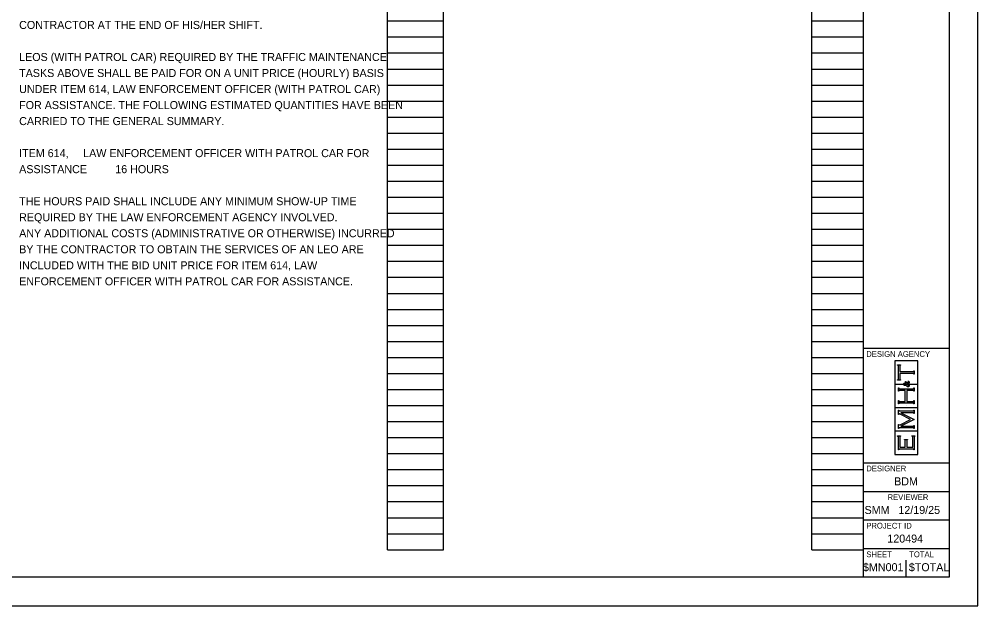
# Model space of a CAD drawing. Extents: x 0 to 34, y 0 to 22.
# Drawn here: x 17.24 to 34, y 0 to 10.25 of the extents above; entities that cross this region are included whole.
import ezdxf

# ---------------------------------------------------------------- set-up
doc = ezdxf.new("R2010")
doc.units = 0
for name, color, linetype in [('SH_Border', 7, 'Continuous'), ('SH_Cut_Line', 7, 'Continuous'), ('SH_Data', 7, 'Continuous'), ('SH_Text', 7, 'Continuous')]:
    doc.layers.add(name, color=color, linetype=linetype)

msp = doc.modelspace()

# ---------------------------------------------------------------- linework, layer by layer
at = {"layer": 'SH_Border'}
for p, q in [((32, 0.5), (32, 21.5)), ((32, 4.5), (33.5, 4.5)), ((32, 2.5), (33.5, 2.5)), ((32, 2), (33.5, 2)), ((32, 1.5), (33.5, 1.5)), ((32, 1), (33.5, 1))]:
    msp.add_line(p, q, dxfattribs=at)
msp.add_lwpolyline([(1.5, 21.5), (33.5, 21.5), (33.5, 0.5), (1.5, 0.5)], close=True, dxfattribs=at)
at = {"layer": 'SH_Cut_Line'}
msp.add_lwpolyline([(0, 0), (34, 0), (34, 22), (0, 22)], close=True, dxfattribs=at)
at = {"layer": 'SH_Data'}
for p, q in [((23.68, 0.98), (23.68, 21.14)), ((24.66, 0.98), (24.66, 21.14)), ((31.1, 0.98), (31.1, 21.14)), ((32, 0.98), (32, 21.14)), ((23.68, 10.22), (24.66, 10.22)), ((31.1, 10.22), (32, 10.22)), ((23.68, 9.94), (24.66, 9.94)), ((31.1, 9.94), (32, 9.94)), ((23.68, 9.66), (24.66, 9.66)), ((31.1, 9.66), (32, 9.66)), ((23.68, 9.38), (24.66, 9.38)), ((31.1, 9.38), (32, 9.38)), ((23.68, 9.1), (24.66, 9.1)), ((31.1, 9.1), (32, 9.1)), ((23.68, 8.82), (24.66, 8.82)), ((31.1, 8.82), (32, 8.82)), ((23.68, 8.54), (24.66, 8.54)), ((31.1, 8.54), (32, 8.54)), ((23.68, 8.26), (24.66, 8.26)), ((31.1, 8.26), (32, 8.26)), ((23.68, 7.98), (24.66, 7.98)), ((31.1, 7.98), (32, 7.98)), ((23.68, 7.7), (24.66, 7.7)), ((31.1, 7.7), (32, 7.7)), ((23.68, 7.42), (24.66, 7.42)), ((31.1, 7.42), (32, 7.42)), ((23.68, 7.14), (24.66, 7.14)), ((31.1, 7.14), (32, 7.14)), ((23.68, 6.86), (24.66, 6.86)), ((31.1, 6.86), (32, 6.86)), ((23.68, 6.58), (24.66, 6.58)), ((31.1, 6.58), (32, 6.58)), ((23.68, 6.3), (24.66, 6.3)), ((31.1, 6.3), (32, 6.3)), ((23.68, 6.02), (24.66, 6.02)), ((31.1, 6.02), (32, 6.02)), ((23.68, 5.74), (24.66, 5.74)), ((31.1, 5.74), (32, 5.74)), ((23.68, 5.46), (24.66, 5.46)), ((31.1, 5.46), (32, 5.46)), ((23.68, 5.18), (24.66, 5.18)), ((31.1, 5.18), (32, 5.18)), ((23.68, 4.9), (24.66, 4.9)), ((31.1, 4.9), (32, 4.9)), ((23.68, 4.62), (24.66, 4.62)), ((31.1, 4.62), (32, 4.62)), ((23.68, 4.34), (24.66, 4.34)), ((31.1, 4.34), (32, 4.34)), ((32.952, 4.279), (32.547, 4.279)), ((32.547, 4.279), (32.547, 3.875)), ((32.598, 4.204), (32.598, 4.211)), ((32.598, 4.211), (32.65, 4.211)), ((32.603, 4.203), (32.598, 4.204)), ((32.606, 4.201), (32.603, 4.203)), ((32.608, 4.199), (32.606, 4.201)), ((32.61, 4.196), (32.608, 4.199)), ((32.611, 4.192), (32.61, 4.196)), ((32.611, 4.187), (32.611, 4.192)), ((32.638, 4.196), (32.637, 4.192)), ((32.637, 4.192), (32.637, 4.187)), ((32.64, 4.199), (32.638, 4.196)), ((32.642, 4.201), (32.64, 4.199)), ((32.645, 4.203), (32.642, 4.201)), ((32.65, 4.204), (32.645, 4.203)), ((32.65, 4.211), (32.65, 4.204)), ((32.952, 3.875), (32.952, 4.279)), ((23.68, 4.06), (24.66, 4.06)), ((31.1, 4.06), (32, 4.06)), ((32.611, 3.968), (32.611, 4.187)), ((32.637, 4.187), (32.637, 4.093)), ((32.637, 4.093), (32.864, 4.093)), ((32.864, 4.061), (32.637, 4.061)), ((32.637, 4.061), (32.637, 3.968)), ((32.864, 4.093), (32.869, 4.093)), ((32.87, 4.061), (32.864, 4.061)), ((32.869, 4.093), (32.873, 4.094)), ((32.874, 4.06), (32.87, 4.061)), ((32.873, 4.094), (32.876, 4.096)), ((32.876, 4.059), (32.874, 4.06)), ((32.876, 4.096), (32.878, 4.097)), ((32.878, 4.057), (32.876, 4.059)), ((32.878, 4.097), (32.88, 4.101)), ((32.88, 4.053), (32.878, 4.057)), ((32.88, 4.101), (32.881, 4.106)), ((32.881, 4.048), (32.88, 4.053)), ((32.881, 4.106), (32.888, 4.106)), ((32.888, 4.048), (32.881, 4.048)), ((32.888, 4.106), (32.888, 4.048)), ((32.547, 3.875), (32.696, 3.875)), ((32.696, 3.869), (32.547, 3.869)), ((32.547, 3.869), (32.547, 3.465)), ((32.598, 3.95), (32.603, 3.951)), ((32.598, 3.944), (32.598, 3.95)), ((32.65, 3.944), (32.598, 3.944)), ((32.603, 3.951), (32.606, 3.953)), ((32.606, 3.953), (32.608, 3.955)), ((32.608, 3.955), (32.61, 3.958)), ((32.61, 3.958), (32.611, 3.962)), ((32.611, 3.962), (32.611, 3.968)), ((32.637, 3.968), (32.637, 3.962)), ((32.637, 3.962), (32.638, 3.958)), ((32.638, 3.958), (32.64, 3.955)), ((32.64, 3.955), (32.642, 3.953)), ((32.642, 3.953), (32.645, 3.951)), ((32.645, 3.951), (32.65, 3.95)), ((32.65, 3.95), (32.65, 3.944)), ((32.696, 3.875), (32.696, 3.869)), ((32.703, 3.879), (32.705, 3.883)), ((32.703, 3.873), (32.703, 3.879)), ((32.703, 3.868), (32.703, 3.873)), ((32.705, 3.863), (32.703, 3.868)), ((32.705, 3.883), (32.708, 3.887)), ((32.708, 3.858), (32.705, 3.863)), ((32.708, 3.887), (32.711, 3.89)), ((32.709, 3.879), (32.708, 3.876)), ((32.708, 3.876), (32.708, 3.873)), ((32.708, 3.873), (32.708, 3.869)), ((32.708, 3.869), (32.71, 3.866)), ((32.712, 3.853), (32.708, 3.858)), ((32.712, 3.881), (32.709, 3.879)), ((32.71, 3.866), (32.712, 3.864)), ((32.711, 3.89), (32.715, 3.892)), ((32.714, 3.883), (32.712, 3.881)), ((32.712, 3.864), (32.715, 3.862)), ((32.716, 3.884), (32.714, 3.883)), ((32.715, 3.892), (32.72, 3.892)), ((32.715, 3.862), (32.718, 3.861)), ((32.72, 3.884), (32.716, 3.884)), ((32.718, 3.861), (32.721, 3.861)), ((32.72, 3.892), (32.725, 3.892)), ((32.724, 3.884), (32.72, 3.884)), ((32.721, 3.861), (32.723, 3.861)), ((32.723, 3.861), (32.725, 3.862)), ((32.728, 3.882), (32.724, 3.884)), ((32.725, 3.892), (32.729, 3.89)), ((32.725, 3.862), (32.728, 3.862)), ((32.731, 3.88), (32.728, 3.882)), ((32.728, 3.862), (32.731, 3.863)), ((32.729, 3.89), (32.732, 3.887)), ((32.734, 3.877), (32.731, 3.88)), ((32.731, 3.863), (32.735, 3.865)), ((32.732, 3.887), (32.736, 3.883)), ((32.737, 3.872), (32.734, 3.877)), ((32.735, 3.865), (32.74, 3.867)), ((32.736, 3.883), (32.74, 3.878)), ((32.74, 3.867), (32.737, 3.872)), ((32.738, 3.893), (32.738, 3.922)), ((32.738, 3.922), (32.741, 3.922)), ((32.741, 3.893), (32.738, 3.893)), ((32.74, 3.878), (32.744, 3.869)), ((32.741, 3.922), (32.741, 3.918)), ((32.741, 3.918), (32.742, 3.915)), ((32.742, 3.896), (32.741, 3.895)), ((32.741, 3.895), (32.741, 3.893)), ((32.746, 3.855), (32.741, 3.853)), ((32.742, 3.915), (32.743, 3.913)), ((32.743, 3.897), (32.742, 3.896)), ((32.743, 3.913), (32.745, 3.911)), ((32.745, 3.899), (32.743, 3.897)), ((32.744, 3.869), (32.754, 3.875)), ((32.745, 3.911), (32.749, 3.908)), ((32.746, 3.899), (32.745, 3.899)), ((32.748, 3.899), (32.746, 3.899)), ((32.752, 3.844), (32.746, 3.855)), ((32.755, 3.899), (32.748, 3.899)), ((32.749, 3.908), (32.756, 3.904)), ((32.756, 3.86), (32.751, 3.857)), ((32.751, 3.857), (32.754, 3.852)), ((32.754, 3.875), (32.764, 3.881)), ((32.763, 3.895), (32.755, 3.899)), ((32.756, 3.904), (32.763, 3.9)), ((32.761, 3.863), (32.756, 3.86)), ((32.764, 3.865), (32.761, 3.863)), ((32.763, 3.9), (32.77, 3.896)), ((32.772, 3.887), (32.763, 3.895)), ((32.764, 3.881), (32.772, 3.887)), ((32.768, 3.867), (32.764, 3.865)), ((32.774, 3.872), (32.768, 3.867)), ((32.77, 3.896), (32.776, 3.891)), ((32.782, 3.878), (32.774, 3.872)), ((32.776, 3.891), (32.781, 3.895)), ((32.779, 3.923), (32.781, 3.926)), ((32.782, 3.922), (32.779, 3.923)), ((32.781, 3.926), (32.787, 3.924)), ((32.781, 3.895), (32.784, 3.898)), ((32.785, 3.921), (32.782, 3.922)), ((32.786, 3.873), (32.782, 3.878)), ((32.784, 3.898), (32.786, 3.901)), ((32.786, 3.919), (32.785, 3.921)), ((32.788, 3.917), (32.786, 3.919)), ((32.786, 3.901), (32.788, 3.904)), ((32.791, 3.886), (32.786, 3.881)), ((32.786, 3.881), (32.791, 3.876)), ((32.788, 3.869), (32.786, 3.873)), ((32.787, 3.924), (32.792, 3.921)), ((32.789, 3.914), (32.788, 3.917)), ((32.788, 3.904), (32.789, 3.908)), ((32.79, 3.867), (32.788, 3.869)), ((32.789, 3.911), (32.789, 3.914)), ((32.789, 3.908), (32.789, 3.911)), ((32.791, 3.864), (32.79, 3.867)), ((32.794, 3.89), (32.791, 3.886)), ((32.791, 3.876), (32.795, 3.87)), ((32.791, 3.861), (32.791, 3.864)), ((32.791, 3.859), (32.791, 3.861)), ((32.791, 3.853), (32.791, 3.859)), ((32.792, 3.921), (32.795, 3.918)), ((32.796, 3.894), (32.794, 3.89)), ((32.795, 3.918), (32.798, 3.914)), ((32.795, 3.87), (32.797, 3.866)), ((32.798, 3.897), (32.796, 3.894)), ((32.797, 3.866), (32.798, 3.861)), ((32.798, 3.914), (32.799, 3.91)), ((32.799, 3.901), (32.798, 3.897)), ((32.798, 3.861), (32.799, 3.857)), ((32.799, 3.91), (32.799, 3.905)), ((32.799, 3.905), (32.799, 3.901)), ((32.803, 3.869), (32.799, 3.875)), ((32.799, 3.875), (32.952, 3.875)), ((32.799, 3.857), (32.799, 3.852)), ((32.952, 3.869), (32.803, 3.869)), ((32.952, 3.465), (32.952, 3.869)), ((23.68, 3.78), (24.66, 3.78)), ((31.1, 3.78), (32, 3.78)), ((32.611, 3.749), (32.611, 3.807)), ((32.611, 3.807), (32.617, 3.807)), ((32.617, 3.749), (32.611, 3.749)), ((32.617, 3.807), (32.619, 3.802)), ((32.618, 3.754), (32.617, 3.749)), ((32.62, 3.758), (32.618, 3.754)), ((32.619, 3.802), (32.62, 3.798)), ((32.62, 3.798), (32.623, 3.797)), ((32.623, 3.76), (32.62, 3.758)), ((32.623, 3.797), (32.625, 3.795)), ((32.625, 3.761), (32.623, 3.76)), ((32.625, 3.795), (32.629, 3.794)), ((32.629, 3.762), (32.625, 3.761)), ((32.629, 3.794), (32.635, 3.794)), ((32.635, 3.762), (32.629, 3.762)), ((32.635, 3.794), (32.864, 3.794)), ((32.732, 3.762), (32.635, 3.762)), ((32.718, 3.85), (32.712, 3.853)), ((32.726, 3.85), (32.718, 3.85)), ((32.729, 3.85), (32.726, 3.85)), ((32.731, 3.85), (32.729, 3.85)), ((32.734, 3.851), (32.731, 3.85)), ((32.732, 3.572), (32.732, 3.762)), ((32.737, 3.852), (32.734, 3.851)), ((32.741, 3.853), (32.737, 3.852)), ((32.757, 3.837), (32.752, 3.844)), ((32.754, 3.852), (32.757, 3.848)), ((32.757, 3.848), (32.761, 3.845)), ((32.763, 3.833), (32.757, 3.837)), ((32.864, 3.762), (32.759, 3.762)), ((32.759, 3.762), (32.759, 3.572)), ((32.761, 3.845), (32.765, 3.843)), ((32.768, 3.829), (32.763, 3.833)), ((32.765, 3.843), (32.769, 3.841)), ((32.774, 3.827), (32.768, 3.829)), ((32.769, 3.841), (32.773, 3.841)), ((32.773, 3.841), (32.778, 3.841)), ((32.779, 3.827), (32.774, 3.827)), ((32.778, 3.841), (32.782, 3.843)), ((32.785, 3.827), (32.779, 3.827)), ((32.782, 3.843), (32.786, 3.846)), ((32.79, 3.829), (32.785, 3.827)), ((32.786, 3.846), (32.789, 3.849)), ((32.789, 3.849), (32.791, 3.853)), ((32.793, 3.834), (32.79, 3.829)), ((32.797, 3.838), (32.793, 3.834)), ((32.799, 3.844), (32.797, 3.838)), ((32.799, 3.852), (32.799, 3.844)), ((32.864, 3.794), (32.869, 3.794)), ((32.87, 3.762), (32.864, 3.762)), ((32.869, 3.794), (32.873, 3.795)), ((32.874, 3.761), (32.87, 3.762)), ((32.873, 3.795), (32.876, 3.797)), ((32.876, 3.76), (32.874, 3.761)), ((32.876, 3.797), (32.878, 3.798)), ((32.878, 3.758), (32.876, 3.76)), ((32.878, 3.798), (32.88, 3.802)), ((32.88, 3.754), (32.878, 3.758)), ((32.88, 3.802), (32.881, 3.807)), ((32.881, 3.749), (32.88, 3.754)), ((32.881, 3.807), (32.888, 3.807)), ((32.888, 3.749), (32.881, 3.749)), ((32.888, 3.807), (32.888, 3.749)), ((32.611, 3.527), (32.611, 3.585)), ((32.611, 3.585), (32.617, 3.585)), ((32.617, 3.527), (32.611, 3.527)), ((32.617, 3.585), (32.619, 3.58)), ((32.618, 3.532), (32.617, 3.527)), ((32.62, 3.536), (32.618, 3.532)), ((32.619, 3.58), (32.62, 3.576)), ((32.62, 3.576), (32.623, 3.574)), ((32.623, 3.537), (32.62, 3.536)), ((32.623, 3.574), (32.625, 3.573)), ((32.625, 3.539), (32.623, 3.537)), ((32.625, 3.573), (32.629, 3.572)), ((32.629, 3.54), (32.625, 3.539)), ((32.629, 3.572), (32.635, 3.572)), ((32.635, 3.54), (32.629, 3.54)), ((32.635, 3.572), (32.732, 3.572)), ((32.864, 3.54), (32.635, 3.54)), ((32.759, 3.572), (32.864, 3.572)), ((32.864, 3.572), (32.87, 3.572)), ((32.87, 3.54), (32.864, 3.54)), ((32.87, 3.572), (32.874, 3.573)), ((32.874, 3.539), (32.87, 3.54)), ((32.874, 3.573), (32.876, 3.574)), ((32.876, 3.538), (32.874, 3.539)), ((32.876, 3.574), (32.878, 3.576)), ((32.878, 3.536), (32.876, 3.538)), ((32.878, 3.576), (32.88, 3.58)), ((32.88, 3.532), (32.878, 3.536)), ((32.88, 3.58), (32.881, 3.585)), ((32.881, 3.527), (32.88, 3.532)), ((32.881, 3.585), (32.888, 3.585)), ((32.888, 3.527), (32.881, 3.527)), ((32.888, 3.585), (32.888, 3.527)), ((23.68, 3.5), (24.66, 3.5)), ((31.1, 3.5), (32, 3.5)), ((32.547, 3.465), (32.952, 3.465)), ((32.952, 3.459), (32.547, 3.459)), ((32.547, 3.459), (32.547, 3.055)), ((32.611, 3.345), (32.611, 3.418)), ((32.611, 3.418), (32.617, 3.418)), ((32.617, 3.418), (32.619, 3.412)), ((32.619, 3.412), (32.62, 3.409)), ((32.62, 3.409), (32.623, 3.407)), ((32.622, 3.355), (32.62, 3.352)), ((32.626, 3.355), (32.622, 3.355)), ((32.623, 3.407), (32.625, 3.405)), ((32.625, 3.405), (32.629, 3.405)), ((32.629, 3.355), (32.626, 3.355)), ((32.629, 3.405), (32.635, 3.405)), ((32.633, 3.353), (32.629, 3.355)), ((32.64, 3.35), (32.633, 3.353)), ((32.635, 3.405), (32.864, 3.405)), ((32.864, 3.373), (32.654, 3.373)), ((32.654, 3.373), (32.888, 3.255)), ((32.75, 3.5), (32.75, 3.5)), ((32.864, 3.405), (32.869, 3.405)), ((32.87, 3.373), (32.864, 3.373)), ((32.869, 3.405), (32.873, 3.405)), ((32.874, 3.372), (32.87, 3.373)), ((32.873, 3.405), (32.876, 3.407)), ((32.876, 3.37), (32.874, 3.372)), ((32.876, 3.407), (32.878, 3.409)), ((32.878, 3.369), (32.876, 3.37)), ((32.878, 3.409), (32.88, 3.412)), ((32.88, 3.365), (32.878, 3.369)), ((32.88, 3.412), (32.881, 3.418)), ((32.881, 3.36), (32.88, 3.365)), ((32.881, 3.418), (32.888, 3.418)), ((32.888, 3.36), (32.881, 3.36)), ((32.888, 3.418), (32.888, 3.36)), ((32.952, 3.055), (32.952, 3.459)), ((23.68, 3.22), (24.66, 3.22)), ((31.1, 3.22), (32, 3.22)), ((32.617, 3.345), (32.611, 3.345)), ((32.62, 3.352), (32.617, 3.345)), ((32.825, 3.257), (32.64, 3.35)), ((32.641, 3.165), (32.825, 3.257)), ((32.888, 3.255), (32.654, 3.138)), ((32.547, 3.055), (32.952, 3.055)), ((32.952, 3.049), (32.547, 3.049)), ((32.547, 3.049), (32.547, 2.645)), ((32.611, 3.096), (32.611, 3.168)), ((32.611, 3.168), (32.617, 3.168)), ((32.617, 3.096), (32.611, 3.096)), ((32.617, 3.168), (32.62, 3.162)), ((32.618, 3.102), (32.617, 3.096)), ((32.62, 3.105), (32.618, 3.102)), ((32.62, 3.162), (32.622, 3.158)), ((32.623, 3.107), (32.62, 3.105)), ((32.622, 3.158), (32.626, 3.158)), ((32.625, 3.109), (32.623, 3.107)), ((32.629, 3.109), (32.625, 3.109)), ((32.626, 3.158), (32.627, 3.158)), ((32.627, 3.158), (32.633, 3.161)), ((32.635, 3.109), (32.629, 3.109)), ((32.633, 3.161), (32.641, 3.165)), ((32.864, 3.109), (32.635, 3.109)), ((32.654, 3.138), (32.864, 3.138)), ((32.864, 3.138), (32.869, 3.138)), ((32.87, 3.109), (32.864, 3.109)), ((32.869, 3.138), (32.873, 3.139)), ((32.874, 3.109), (32.87, 3.109)), ((32.873, 3.139), (32.876, 3.141)), ((32.876, 3.107), (32.874, 3.109)), ((32.876, 3.141), (32.878, 3.143)), ((32.878, 3.105), (32.876, 3.107)), ((32.878, 3.143), (32.88, 3.146)), ((32.88, 3.102), (32.878, 3.105)), ((32.88, 3.146), (32.881, 3.151)), ((32.881, 3.096), (32.88, 3.102)), ((32.881, 3.151), (32.888, 3.151)), ((32.888, 3.096), (32.881, 3.096)), ((32.888, 3.151), (32.888, 3.096)), ((32.952, 2.645), (32.952, 3.049)), ((23.68, 2.94), (24.66, 2.94)), ((31.1, 2.94), (32, 2.94)), ((32.598, 2.962), (32.598, 2.969)), ((32.598, 2.969), (32.65, 2.969)), ((32.603, 2.961), (32.598, 2.962)), ((32.606, 2.959), (32.603, 2.961)), ((32.608, 2.957), (32.606, 2.959)), ((32.61, 2.955), (32.608, 2.957)), ((32.611, 2.951), (32.61, 2.955)), ((32.611, 2.945), (32.611, 2.951)), ((32.611, 2.725), (32.611, 2.945)), ((32.64, 2.957), (32.638, 2.955)), ((32.638, 2.955), (32.638, 2.951)), ((32.638, 2.951), (32.638, 2.945)), ((32.638, 2.945), (32.638, 2.77)), ((32.642, 2.959), (32.64, 2.957)), ((32.645, 2.961), (32.642, 2.959)), ((32.65, 2.962), (32.645, 2.961)), ((32.65, 2.969), (32.65, 2.962)), ((32.719, 2.902), (32.719, 2.908)), ((32.719, 2.908), (32.772, 2.908)), ((32.724, 2.901), (32.719, 2.902)), ((32.728, 2.899), (32.724, 2.901)), ((32.729, 2.896), (32.728, 2.899)), ((32.731, 2.894), (32.729, 2.896)), ((32.732, 2.89), (32.731, 2.894)), ((32.732, 2.884), (32.732, 2.89)), ((32.732, 2.77), (32.732, 2.884)), ((32.76, 2.894), (32.759, 2.89)), ((32.759, 2.89), (32.759, 2.884)), ((32.759, 2.884), (32.759, 2.77)), ((32.761, 2.896), (32.76, 2.894)), ((32.763, 2.899), (32.761, 2.896)), ((32.767, 2.901), (32.763, 2.899)), ((32.772, 2.902), (32.767, 2.901)), ((32.772, 2.908), (32.772, 2.902)), ((32.848, 2.965), (32.848, 2.972)), ((32.848, 2.972), (32.901, 2.972)), ((32.853, 2.964), (32.848, 2.965)), ((32.857, 2.962), (32.853, 2.964)), ((32.859, 2.96), (32.857, 2.962)), ((32.86, 2.958), (32.859, 2.96)), ((32.861, 2.953), (32.86, 2.958)), ((32.861, 2.948), (32.861, 2.953)), ((32.861, 2.77), (32.861, 2.948)), ((32.889, 2.957), (32.888, 2.953)), ((32.888, 2.953), (32.888, 2.948)), ((32.888, 2.948), (32.888, 2.725)), ((32.891, 2.96), (32.889, 2.957)), ((32.892, 2.962), (32.891, 2.96)), ((32.896, 2.964), (32.892, 2.962)), ((32.901, 2.965), (32.896, 2.964)), ((32.901, 2.972), (32.901, 2.965)), ((32.617, 2.725), (32.611, 2.725)), ((32.619, 2.73), (32.617, 2.725)), ((32.62, 2.734), (32.619, 2.73)), ((32.623, 2.735), (32.62, 2.734)), ((32.625, 2.737), (32.623, 2.735)), ((32.629, 2.738), (32.625, 2.737)), ((32.635, 2.738), (32.629, 2.738)), ((32.864, 2.738), (32.635, 2.738)), ((32.638, 2.77), (32.732, 2.77)), ((32.759, 2.77), (32.861, 2.77)), ((32.87, 2.738), (32.864, 2.738)), ((32.874, 2.737), (32.87, 2.738)), ((32.876, 2.735), (32.874, 2.737)), ((32.878, 2.734), (32.876, 2.735)), ((32.88, 2.73), (32.878, 2.734)), ((32.881, 2.725), (32.88, 2.73)), ((32.888, 2.725), (32.881, 2.725)), ((23.68, 2.66), (24.66, 2.66)), ((31.1, 2.66), (32, 2.66)), ((32.547, 2.645), (32.952, 2.645)), ((23.68, 2.38), (24.66, 2.38)), ((31.1, 2.38), (32, 2.38)), ((23.68, 2.1), (24.66, 2.1)), ((31.1, 2.1), (32, 2.1)), ((23.68, 1.82), (24.66, 1.82)), ((31.1, 1.82), (32, 1.82)), ((23.68, 1.54), (24.66, 1.54)), ((31.1, 1.54), (32, 1.54)), ((23.68, 1.26), (24.66, 1.26)), ((31.1, 1.26), (32, 1.26)), ((23.68, 0.98), (24.66, 0.98)), ((31.1, 0.98), (32, 0.98)), ((32.375, 0.675), (32.375, 0.675)), ((32.75, 0.5), (32.75, 0.8))]:
    msp.add_line(p, q, dxfattribs=at)

# ---------------------------------------------------------------- texts
for s, height, p in [('DESIGN AGENCY', 0.1, (32.05, 4.35)), ('DESIGNER', 0.1, (32.05, 2.35)), ('BDM', 0.14, (32.537, 2.105)), ('REVIEWER', 0.1, (32.422, 1.85)), ('SMM', 0.14, (32.02, 1.605)), ('12/19/25', 0.14, (32.611, 1.605)), ('PROJECT ID', 0.1, (32.05, 1.35)), ('120494', 0.14, (32.418, 1.105)), ('SHEET', 0.1, (32.05, 0.85)), ('TOTAL', 0.1, (32.8, 0.85)), ('$MN001', 0.14, (31.992, 0.605)), ('$TOTAL', 0.14, (32.794, 0.605))]:
    msp.add_text(s, height=height, dxfattribs=at).set_placement(p)
at = {"layer": 'SH_Text'}
for s, p in [('CONTRACTOR AT THE END OF HIS/HER SHIFT.\xa0', (17.24, 10.08)), ('LEOS (WITH PATROL CAR) REQUIRED BY THE TRAFFIC MAINTENANCE ', (17.24, 9.52)), ('TASKS ABOVE SHALL BE PAID FOR ON A UNIT PRICE (HOURLY) BASIS ', (17.24, 9.24)), ('UNDER ITEM 614, LAW ENFORCEMENT OFFICER (WITH PATROL CAR) ', (17.24, 8.96)), ('FOR ASSISTANCE. THE FOLLOWING ESTIMATED QUANTITIES HAVE BEEN ', (17.24, 8.68)), ('CARRIED TO THE GENERAL SUMMARY.', (17.24, 8.4)), ('ITEM 614, \xa0', (17.24, 7.84)), ('LAW ENFORCEMENT OFFICER WITH PATROL CAR FOR ', (18.36, 7.84)), ('ASSISTANCE', (17.24, 7.56)), ('16 HOURS', (18.92, 7.56)), ('THE HOURS PAID SHALL INCLUDE ANY MINIMUM SHOW-UP TIME ', (17.24, 7)), ('REQUIRED BY THE LAW ENFORCEMENT AGENCY INVOLVED.', (17.24, 6.72)), ('ANY ADDITIONAL COSTS (ADMINISTRATIVE OR OTHERWISE) INCURRED ', (17.24, 6.44)), ('BY THE CONTRACTOR TO OBTAIN THE SERVICES OF AN\xa0LEO\xa0ARE ', (17.24, 6.16)), ('INCLUDED WITH THE BID UNIT PRICE FOR ITEM 614, LAW ', (17.24, 5.88)), ('ENFORCEMENT OFFICER WITH PATROL CAR FOR ASSISTANCE.', (17.24, 5.6))]:
    msp.add_text(s, height=0.14, rotation=360, dxfattribs=at).set_placement(p)

doc.saveas('drawing.dxf')
